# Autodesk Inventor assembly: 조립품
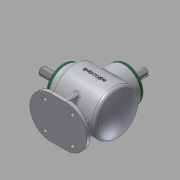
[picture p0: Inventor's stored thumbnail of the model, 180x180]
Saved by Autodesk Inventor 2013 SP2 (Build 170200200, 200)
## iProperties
Created: 2023-01
Part Number: 조립품
Document SubType Name: Assembly
Designer: aa
Author: aa
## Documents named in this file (14)
- C:\Users\aa\Desktop\730106V1028\730106V1028\조립품.iam
- C:\Users\aa\Desktop\730106V1025\본체.ipt
- C:\Users\aa\Desktop\730106V1025\서브 베벨기어.ipt
- C:\Users\aa\Desktop\730106V1025\오일실 17 32 8.ipt
- C:\Users\aa\Desktop\730106V1025\커버.ipt
- C:\Users\aa\Desktop\730106V1025\메인 베벨기어.ipt
- C:\Users\aa\Desktop\730106V1025\베어링 6203.ipt
- C:\Users\aa\Desktop\730106V1025\M4.ipt
- C:\Users\aa\Desktop\730106V1025\서브 축.ipt
- 서브 축.ipt
- C:\Users\aa\Desktop\730106V1025\메인 축.ipt
- 메인 축.ipt
- C:\Users\aa\Desktop\730106V1025\키 4x4.ipt
- C:\Users\aa\Desktop\730106V1025\키 5x5.ipt
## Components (5 placed, 1 different names)
1. M4:2
2. M4:1
3. M4:3
4. M4:4
5. M4:5
